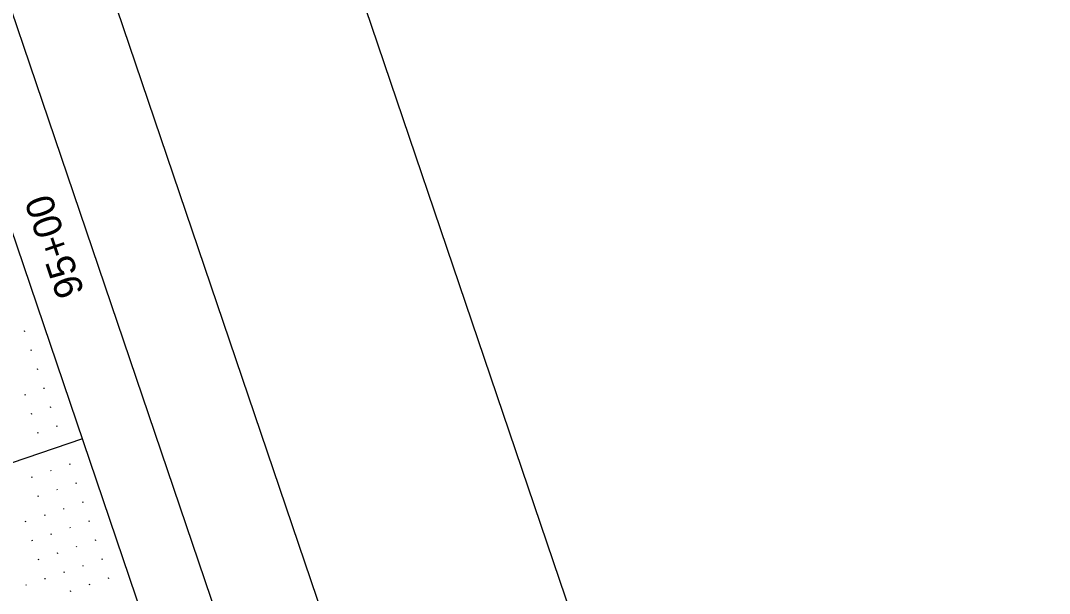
# Model space of a CAD drawing. Extents: x 2150318 to 2152065, y 143281 to 145371.
# Drawn here: x 2151643.3 to 2151899.7, y 144416 to 144558.8 of the extents above; entities that cross this region are included whole.
import ezdxf

# ---------------------------------------------------------------- set-up
doc = ezdxf.new("R2010")
doc.units = 0
for name, color, linetype in [('SHT_Plan_Profile_Sheet_Sta_Txt', 7, 'Continuous'), ('SHT_Plot_Shape_Full', 7, 'Continuous'), ('SHT_Plot_Shape_Half', 7, 'Continuous'), ('SHT_Profile_Grid_Major', 7, 'Continuous'), ('SHT_Profile_Grid_Minor', 7, 'Continuous'), ('SHT_Sheet_Border', 7, 'Continuous')]:
    doc.layers.add(name, color=color, linetype=linetype)

msp = doc.modelspace()

# ---------------------------------------------------------------- linework, layer by layer
at = {"layer": 'SHT_Plot_Shape_Full'}
msp.add_lwpolyline([(2150896.74, 143280.62), (2150318.46, 144985.2), (2151454.85, 145370.71), (2152033.12, 143666.13)], close=True, dxfattribs=at)
at = {"layer": 'SHT_Plot_Shape_Half'}
msp.add_lwpolyline([(2150909.49, 143371.4), (2150363.35, 144981.29), (2151405.04, 145334.68), (2151951.18, 143724.79)], close=True, dxfattribs=at)
at = {"layer": 'SHT_Profile_Grid_Major'}
msp.add_line((2151658.75, 144454.53), (2151185.25, 144293.89), dxfattribs=at)
at = {"layer": 'SHT_Profile_Grid_Minor'}
for p, q in [((2151644.41, 144481.21), (2151644.33, 144481.45)), ((2151646.02, 144476.48), (2151645.94, 144476.71)), ((2151647.63, 144471.74), (2151647.54, 144471.98)), ((2151649.23, 144467.01), (2151649.15, 144467.24)), ((2151644.5, 144465.4), (2151644.42, 144465.64)), ((2151650.84, 144462.27), (2151650.76, 144462.51)), ((2151646.1, 144460.66), (2151646.02, 144460.9)), ((2151652.44, 144457.54), (2151652.36, 144457.77)), ((2151647.71, 144455.93), (2151647.63, 144456.17)), ((2151650.92, 144446.46), (2151650.84, 144446.7)), ((2151655.66, 144448.07), (2151655.58, 144448.3)), ((2151646.19, 144444.85), (2151646.11, 144445.09)), ((2151652.53, 144441.73), (2151652.45, 144441.96)), ((2151657.26, 144443.33), (2151657.18, 144443.57)), ((2151647.79, 144440.12), (2151647.71, 144440.36)), ((2151658.87, 144438.6), (2151658.79, 144438.83)), ((2151654.13, 144436.99), (2151654.05, 144437.23)), ((2151644.66, 144433.78), (2151644.58, 144434.01)), ((2151649.4, 144435.38), (2151649.32, 144435.62)), ((2151660.48, 144433.86), (2151660.4, 144434.1)), ((2151651.01, 144430.65), (2151650.93, 144430.89)), ((2151655.74, 144432.26), (2151655.66, 144432.49)), ((2151646.27, 144429.04), (2151646.19, 144429.28)), ((2151662.08, 144429.13), (2151662, 144429.36)), ((2151652.61, 144425.91), (2151652.53, 144426.15)), ((2151657.35, 144427.52), (2151657.27, 144427.76)), ((2151647.88, 144424.31), (2151647.8, 144424.54)), ((2151663.69, 144424.39), (2151663.61, 144424.63)), ((2151654.22, 144421.18), (2151654.14, 144421.42)), ((2151658.95, 144422.79), (2151658.87, 144423.02)), ((2151644.75, 144417.97), (2151644.67, 144418.2)), ((2151649.48, 144419.57), (2151649.4, 144419.81)), ((2151660.56, 144418.05), (2151660.48, 144418.29)), ((2151665.29, 144419.66), (2151665.21, 144419.89)), ((2151655.82, 144416.44), (2151655.74, 144416.68))]:
    msp.add_line(p, q, dxfattribs=at)
at = {"layer": 'SHT_Sheet_Border'}
msp.add_line((2151879.61, 143803.47), (2151457.96, 145046.39), dxfattribs=at)
msp.add_lwpolyline([(2150901.85, 143471.77), (2150395.86, 144963.28), (2151390.2, 145300.6), (2151896.19, 143809.09)], close=True, dxfattribs=at)

# ---------------------------------------------------------------- texts
at = {"layer": 'SHT_Plan_Profile_Sheet_Sta_Txt'}
msp.add_text('95+00', height=7, rotation=108.7393, dxfattribs=at).set_placement((2151659.26, 144491.13))

doc.saveas('drawing.dxf')
